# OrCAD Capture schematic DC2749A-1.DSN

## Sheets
1 PAGE2: size Custom; title: HIGH EFFICIENCY 4 PHASE 120A; rev: 1; company: TM
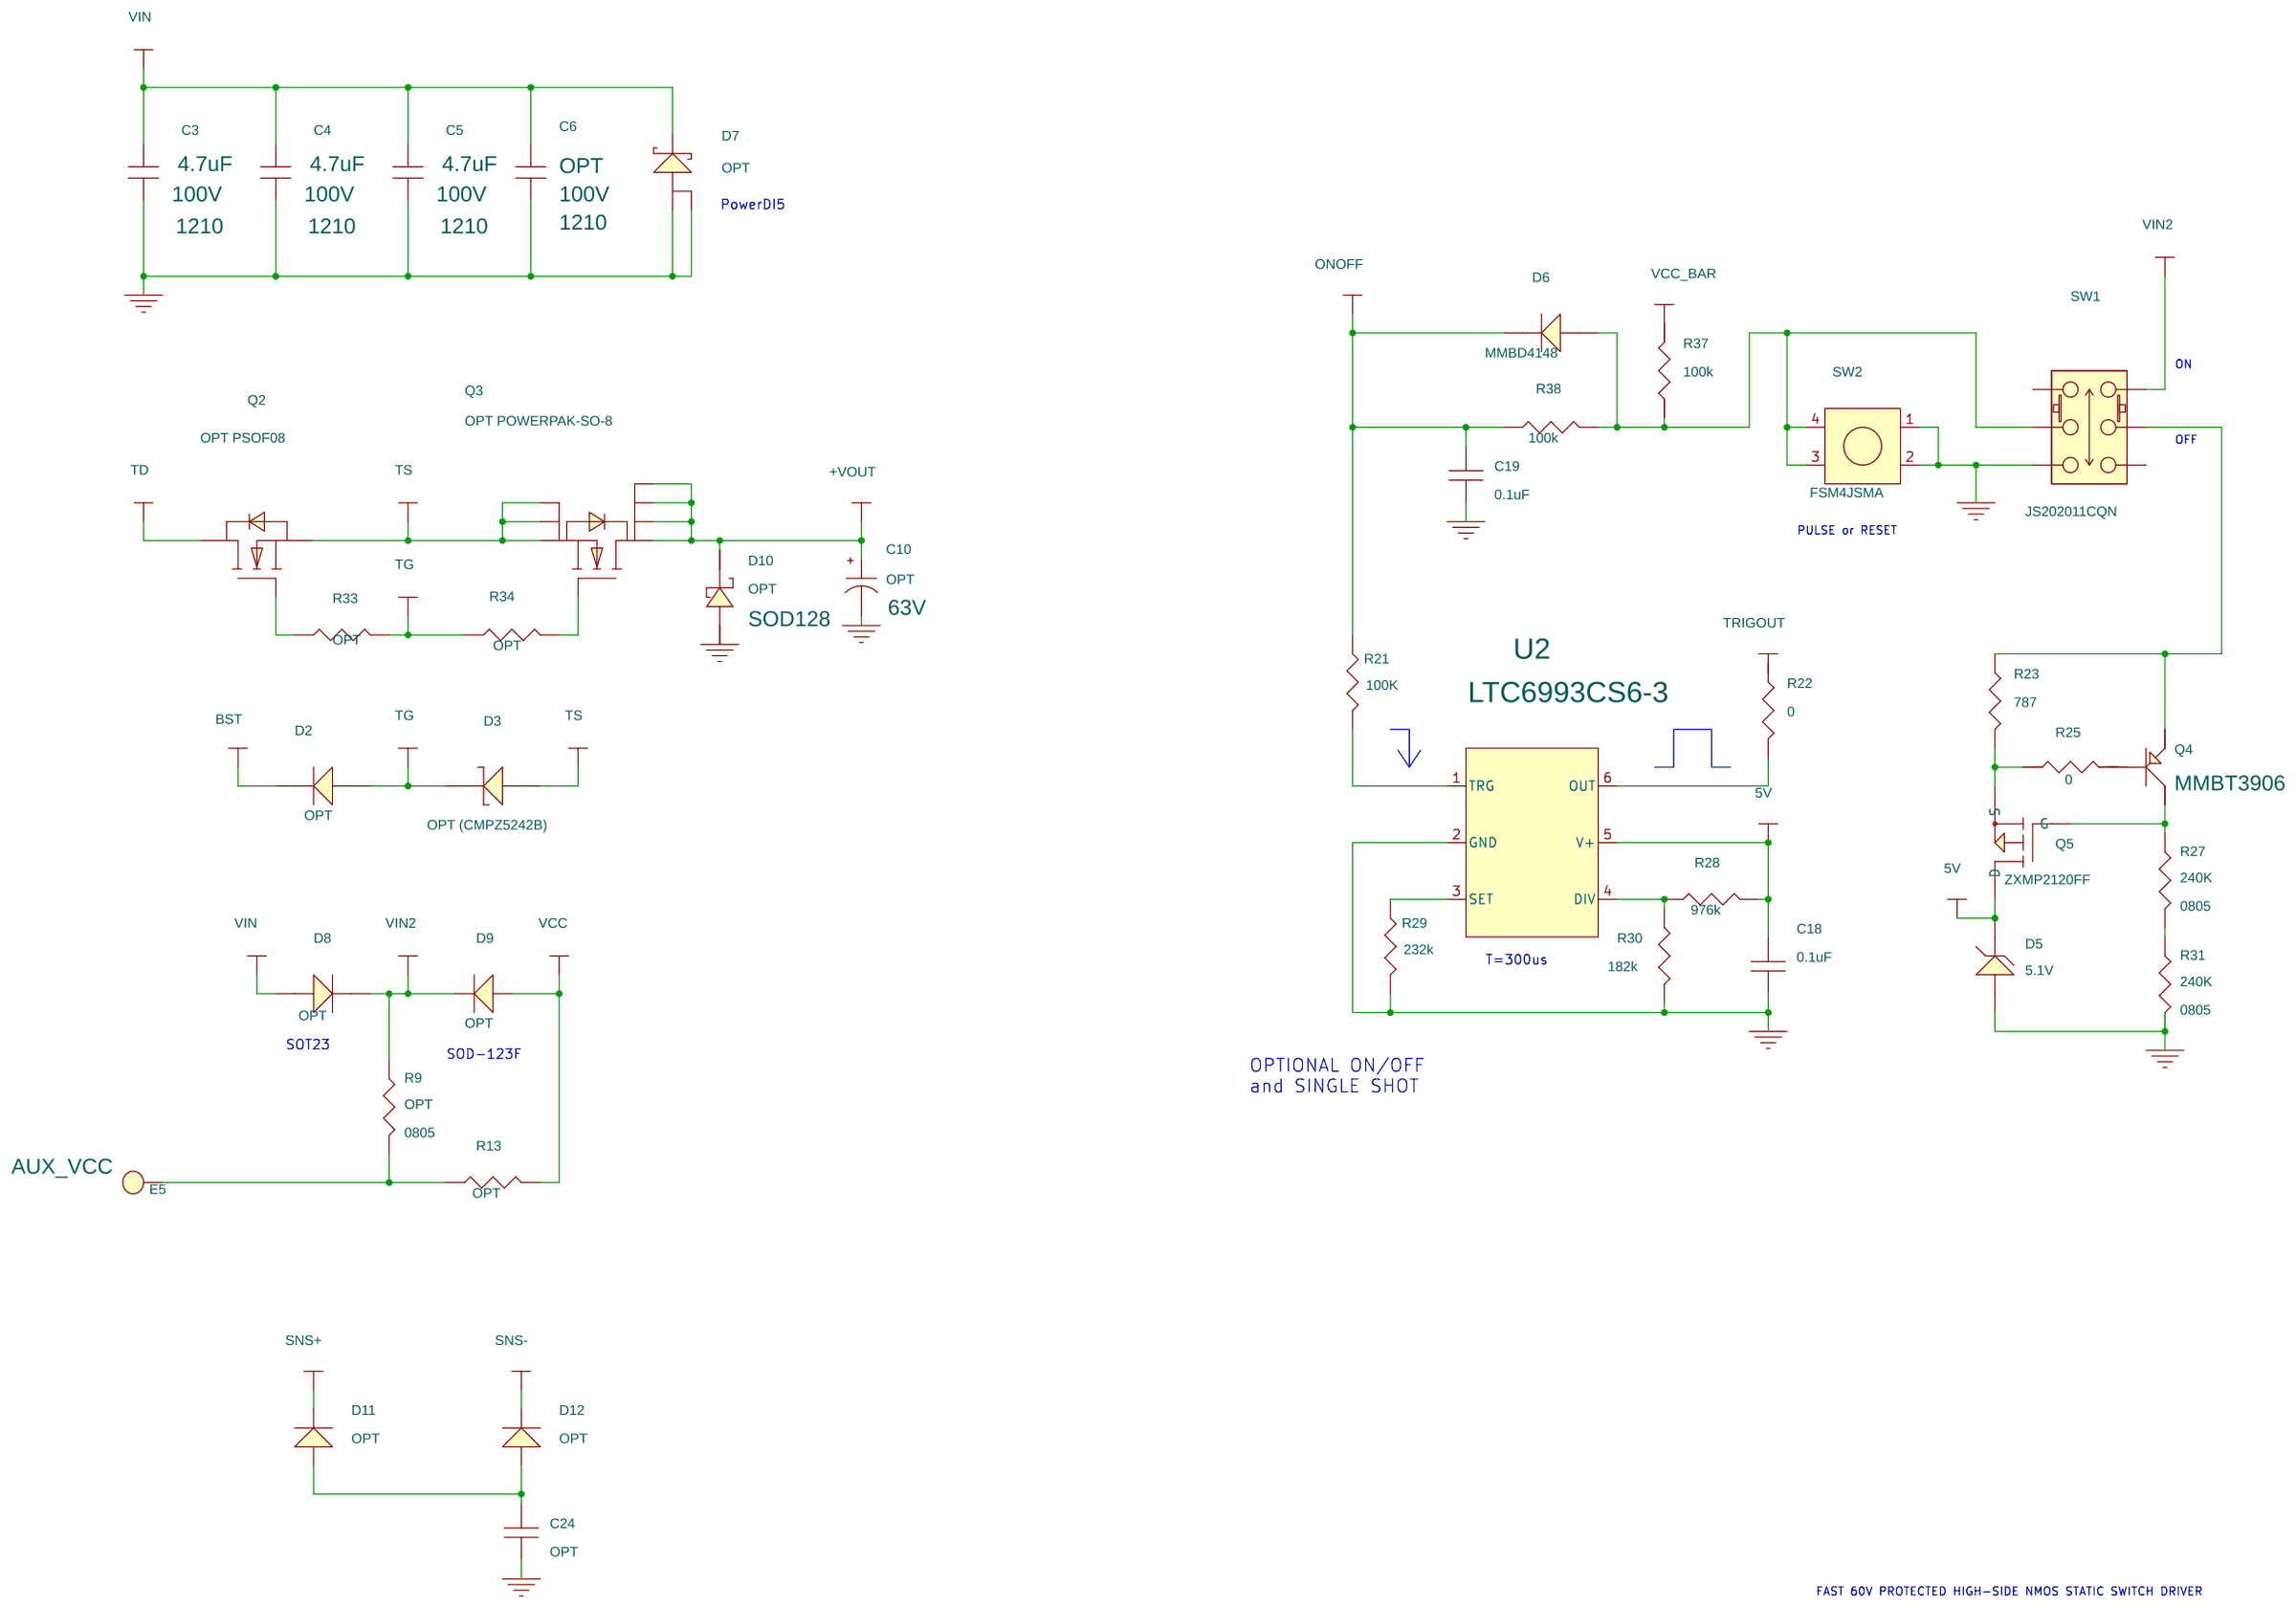
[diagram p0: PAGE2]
2 PAGE1: size Custom
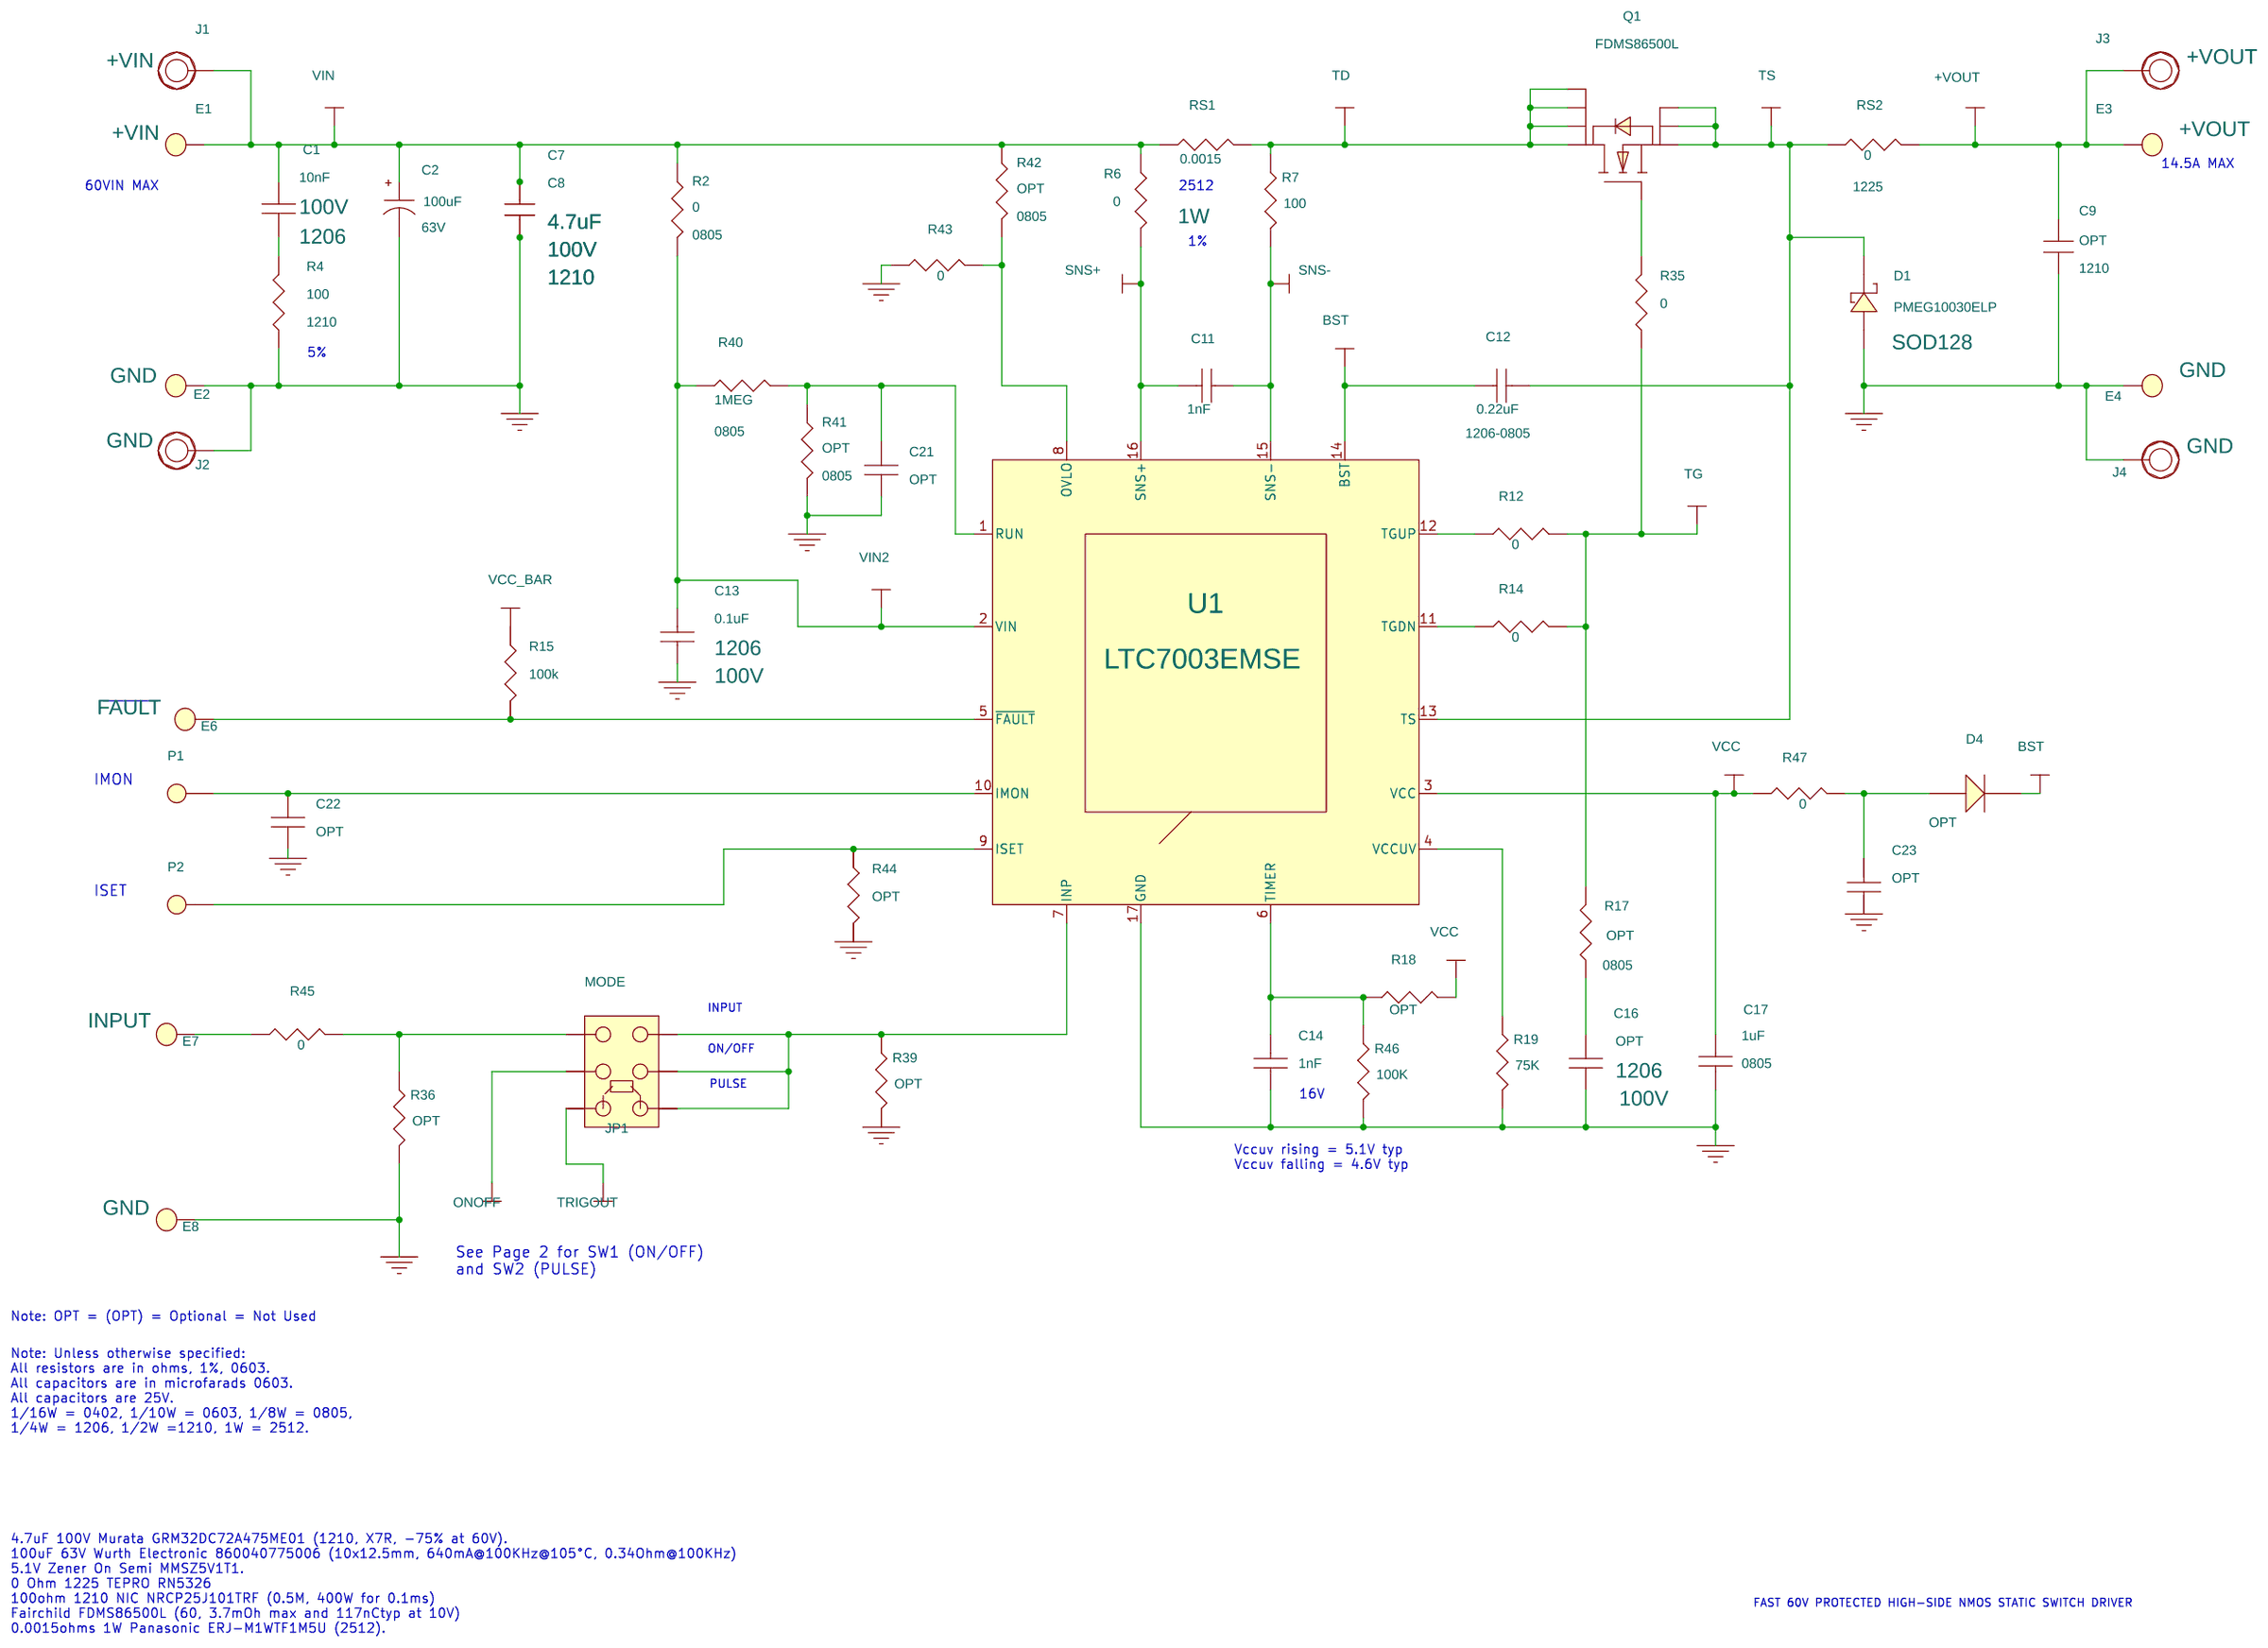
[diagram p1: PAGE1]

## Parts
sheet PAGE1
C1  10nF  [1206]
C2  100uF  [CAP-TH-EE-A-10D]
C7  4.7uF  [1210]
C8  4.7uF  [1210]
C9  OPT  [1210]
C11  1nF  [0603]
C12  0.22uF  [1206-0805]
C13  0.1uF  [1206]
C14  1nF  [0603]
C16  OPT  [1206]
C17  1uF  [0805]
C21  OPT  [0603]
C22  OPT  [0603]
C23  OPT  [0603]
D1  PMEG10030ELP  [SOD128]
D4  OPT  [SOT23]
E1  TURRET  [PAD150-094]
E2  TURRET  [PAD150-094]
E3  TURRET  [PAD150-094]
E4  TURRET  [PAD150-094]
E6  TURRET  [PAD150-094]
E7  TURRET  [PAD150-094]
E8  TURRET  [PAD150-094]
J1  Banana Jack  [KEYSTONE-575-4]
J2  Banana Jack  [KEYSTONE-575-4]
J3  Banana Jack  [KEYSTONE-575-4]
J4  Banana Jack  [KEYSTONE-575-4]
JP1  MODE  [HD2X3-079]
P1  TESTPAD  [PAD060-035]
P2  TESTPAD  [PAD060-035]
Q1  FDMS86500L  [POWERPAK-SO-8]
R2  0  [0805]
R4  100  [1210]
R6  0  [0603]
R7  100  [0603]
R12  0  [0603]
R14  0  [0603]
R15  100k  [0603]
R17  OPT  [0805]
R18  OPT  [0603]
R19  75K  [0603]
R35  0  [0603]
R36  OPT  [0603]
R39  OPT  [0603]
R40  1MEG  [0805]
R41  OPT  [0805]
R42  OPT  [0805]
R43  0  [0603]
R44  OPT  [0603]
R45  0  [0603]
R46  100K  [0603]
R47  0  [0603]
RS1  0.0015  [2512T]
RS2  0  [1225]
U1  LTC7003EMSE  [MSE16]
XJP1  2mm Ctrs.
sheet PAGE2
C3  4.7uF  [1210]
C4  4.7uF  [1210]
C5  4.7uF  [1210]
C6  OPT  [1210]
C10  OPT  [CAP-TH-10D]
C18  0.1uF  [0603]
C19  0.1uF  [0603]
C24  OPT  [0603]
D2  OPT  [SOT23]
D3  OPT (CMPZ5242B)  [SOT23]
D5  MMSZ5V1T1  [SOD-123]
D6  MMBD4148  [SOT23]
D7  OPT  [POWERDI5]
D8  OPT  [SOT23]
D9  OPT  [SOD-123F]
D10  OPT  [SOD128]
D11  OPT  [SOD323]
D12  OPT  [SOD323]
E5  TURRET  [PAD150-094]
Q2  OPT PSOF08  [PWR-PSOF08A-3P]
Q3  OPT POWERPAK-SO-8  [POWERPAK-SO-8]
Q4  MMBT3906  [SOT23B]
Q5  ZXMP2120FF  [SOT23A]
R9  OPT  [0805]
R13  OPT  [0603]
R21  100K  [0603]
R22  0  [0603]
R23  787  [0603]
R25  0  [0603]
R27  240K  [0805]
R28  976k  [0603]
R29  232k  [0603]
R30  182k  [0603]
R31  240K  [0805]
R33  OPT  [0603]
R34  OPT  [0603]
R37  100k  [0603]
R38  100k  [0603]
SW1  JS202011CQN  [JS202011]
SW2  FSM4JSMA  [SW-FSMJSMA]
U2  LTC6993CS6-3  [TSOT23-6]

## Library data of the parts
C1 C16 = 12061C104KAT2A_0: 1ST PART FIELD: 100V; 2ND PART FIELD: 10%, 0206; 3RD PART FIELD: X7R; 4TH PART FIELD: AVX; 7TH PART FIELD: CAP.
C2 = CAP-HVH-10X10.5: 1ST PART FIELD: 63V; 5TH PART FIELD: 10X20
C3-C8 = CAP1210: 1ST PART FIELD: 250V; 2ND PART FIELD: 20%, 1210; 3RD PART FIELD: X7R; 4TH PART FIELD: TDK; 7TH PART FIELD: CAP.; VOLTAGE: 100V
C9 = CAP1210: 1ST PART FIELD: 100V; 2ND PART FIELD: 20%, 1210; 3RD PART FIELD: X7R; 4TH PART FIELD: TDK; 7TH PART FIELD: CAP.
C11 C14 C18 C19 C21-C24 = 12061C104KAT2A_0: 1ST PART FIELD: 25V; 2ND PART FIELD: 10%, 0603; 3RD PART FIELD: NPO; 4TH PART FIELD: AVX; 5TH PART FIELD: 06033A471KAT2A; 7TH PART FIELD: CAP.
C12 = 12061C104KAT2A_0: 1ST PART FIELD: 25V; 2ND PART FIELD: 10%, 0805; 3RD PART FIELD: X7R; 4TH PART FIELD: AVX; 5TH PART FIELD: 0805; 7TH PART FIELD: CAP.
C13 = 12061C104KAT2A_0: 1ST PART FIELD: 200V; 2ND PART FIELD: 10%, 0206; 3RD PART FIELD: X7R; 4TH PART FIELD: AVX; 7TH PART FIELD: CAP.; VOLTAGE: 100V
C17 = TMK316BJ105KL: 1ST PART FIELD: 16V; 2ND PART FIELD: 10%, 0805; 3RD PART FIELD: X7R; 4TH PART FIELD: TAIYO TUDEN; 7TH PART FIELD: CAP.
D1 D10 = DIODE_SCHOTTKY_0
D4 D8 = CMPSH1-4_14
E1 = TURRET_2501-2: 7TH PART FIELD: HOLE,; 9TH PART FIELD: +VIN
E2 E4 = TURRET_2501-2: 7TH PART FIELD: HOLE,; 9TH PART FIELD: GND
E3 = TURRET_2501-2: 7TH PART FIELD: HOLE,; 9TH PART FIELD: +VOUT
E6 = TURRET_2501-2: 9TH PART FIELD: FAULT
E7 = TURRET_2501-2: 9TH PART FIELD: INPUT
E8 = TURRET_2501-2: 9TH PART FIELD: GND
J1 = E-KEY-575_0: 9th Part Field: +VIN
J2 J4 = E-KEY-575_0: 9th Part Field: GND
J3 = E-KEY-575_0: 9th Part Field: +VOUT
JP1 = hdr2X4_0: HEADER, 4PIN, DBL ROW 2mm; Part Number: SAMTEC TMM-104-02-L-D
P1 = P-TP_2
P2 = P-TP_3
Q1 Q3 = SI7456DP: 1ST PART FIELD: 150V; 2ND PART FIELD: POWERPAK SO-8; 3RD PART FIELD: N-CHANNEL; 5TH PART FIELD: Si7450DP; 7TH PART FIELD: FET; opt: *
R2 R9 R17 R27 R31 R40-R42 = AAC-0805: 2ND PART FIELD: 1%, 0805; 7TH PART FIELD: RES.
R4 = AAC-0805: 1ST PART FIELD: 0.5W; 2ND PART FIELD: 5%, 1210; 4TH PART FIELD: NIC; 5TH PART FIELD: NRCP25J101TRF; 7TH PART FIELD: RES.
R6 R7 R12-R15 R18 R19 R21-R23 R25 R28-R30 R33-R39 R43-R47 = AAC-0805: 1ST PART FIELD: 1/16W; 2ND PART FIELD: 1%, 0603; 5TH PART FIELD: CR16-xxxxFM; 7TH PART FIELD: RES.
RS1 = AAC-0805: 1ST PART FIELD: 1W; 2ND PART FIELD: 1%, 0805; 5TH PART FIELD: 1206; 7TH PART FIELD: RES.
RS2 = AAC-0805: 1ST PART FIELD: 1/2W; 2ND PART FIELD: 1%, 1210; 5TH PART FIELD: 1210; 7TH PART FIELD: RES.
U1 = LT1339_64: 3RD PART FIELD: ANALOG; 4TH PART FIELD: LINEAR TECH.; 5TH PART FIELD: LTC7000EMS16E; 7TH PART FIELD: I.C.
XJP1 = Samtec_2SN-BK-G: SHUNT; Part Number: SAMTEC 2SN-BK-G
C10 = CAP-HVH-10X10.5: 1ST PART FIELD: 63V; 5TH PART FIELD: 10X10.5
D2 = CMPSH1-4_12
D3 = CMPSH1-4_16
D5 = MMBZ5248BLT1_0: 1ST PART FIELD: 5.1V; 2ND PART FIELD: 5%, SOD123; 3RD PART FIELD: ZENER; 4TH PART FIELD: DIODES INC.; 7TH PART FIELD: DIODE
D6 = CMPSH1-4_11
D7 = DIODE-PDS3100
D9 D11 D12 = DIODE-CMMR1U-SOD123F
E5 = TURRET_2501-2: 9TH PART FIELD: AUX_VCC
Q2 = SI7456DP_3: 1ST PART FIELD: 150V; 2ND PART FIELD: POWERPAK SO-8; 3RD PART FIELD: N-CHANNEL; 5TH PART FIELD: Si7450DP; 7TH PART FIELD: FET; opt: *
Q4 = MMBT3906LT1_0: 2ND PART FIELD: SOT23; 3RD PART FIELD: PNP; 4TH PART FIELD: ZETEX; 5TH PART FIELD: FMMT718; 7TH PART FIELD: XSTR.
Q5 = MOSFET_P-DIODE_2
SW1 = SW_5: HEADER, 4PIN, DBL ROW 2mm
SW2 = BUTTON_0
U2 = LTC2400_2

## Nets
5V: C18.1 D5.1 Q5.D R28.2 R37.1 U2.5(V+)
GND: C2.2 C3.2 C4.2 C5.2 C6.2 C7.2 C8.2 C9.2 C10.2 C13.2 C14.2 C16.2 C17.2 C18.2 C19.2 C21.2 C22.2 C23.2 C24.2 D1.2(ANODE) D5.2 D7.2 D7.3 D10.2(ANODE) E2.1 E4.1 E8.1 J2.1 J4.1 R4.2 R19.2 R29.2 R30.2 R31.1 R36.2 R39.2 R41.1 R43.2 R44.2 R46.2 SW1.6 SW2.1 SW2.2 U1.17(GND) U2.2(GND)
VCC: C17.1 D9.2 R13.2 R15.1 R18.1 R47.1 U1.3(VCC)
VIN: C1.2 C2.1 C3.1 C4.1 C5.1 C6.1 C7.1 C8.1 D7.1 D8.1(A) E1.1 J1.1 R2.2 R6.1 R42.2 RS1.2
VIN2: C13.1 D8.3(K) D9.1 R2.1 R9.2 R40.2 SW1.1 U1.2(VIN)
+VOUT: C9.1 C10.1 D10.1(CATHODE) E3.1 J3.1 Q3.5 Q3.6 Q3.7 Q3.8 RS2.1
BST: C12.2 D2.3(K) D4.3(K) U1.14(BST)
ONOFF: C19.1 D6.3(K) JP1.4 R21.1 R38.2
SNS+: C11.1 D11.1 R6.2 U1.16(SNS+)
SNS-: C11.2 D12.1 R7.2 U1.15(SNS-)
TD: Q1.5 Q1.6 Q1.7 Q1.8 Q2.D R7.1 RS1.1
TG: D2.1(A) D3.3(K) R12.2 R14.2 R17.1 R33.2 R34.1 R35.1
TRIGOUT: JP1.6 R22.1
TS: C12.1 D1.1(CATHODE) D3.1(A) Q1.1 Q1.2 Q1.3 Q2.S Q3.1 Q3.2 Q3.3 RS2.2 U1.13(TS)
N19054060: E6.1 R15.2 U1.5(~{FAULT})
N19054068: C14.1 R18.2 R46.1 U1.6(TIMER)
N19054099: C22.1 P1.1(A) U1.10(IMON)
N19054138: C21.1 R40.1 R41.2 U1.1(RUN)
N19054192: C16.1 R17.2
N19054262: R42.1 R43.1 U1.8(OVLO)
N19054491: Q1.4 R35.2
N19054777: P2.1(A) R44.1 U1.9(ISET)
N19054856: C1.1 R4.1
N19054862: R12.1 U1.12(TGUP)
N19054937: R14.1 U1.11(TGDN)
N19056424: E5.1 R9.1 R13.1
N19056950: Q3.4 R34.2
N19056982: Q2.G R33.1
N19060184: JP1.2 R36.1 R45.2
N19060223: JP1.1 JP1.3 JP1.5 R39.1 U1.7(INP)
N19061333: E7.1 R45.1
N19061526: R19.1 U1.4(VCCUV)
N19068396: R28.1 R30.1 U2.4(DIV)
N19068478: D6.1(A) R37.2 R38.1 SW1.5 SW2.3 SW2.4
N19068494: Q4.E R23.1 SW1.2
N19068588: R21.2 U2.1(TRG)
N19068610: R27.1 R31.2
N19068630: R22.2 U2.6(OUT)
N19068638: Q5.S R23.2 R25.2
N19068729: Q4.C Q5.G R27.2
N19068794: R29.1 U2.3(SET)
N19068796: Q4.B R25.1
N19081929: C23.1 D4.1(A) R47.2
N19103824: C24.1 D11.2 D12.2

Not connected (* = marked no-connect by the designer): SW1 3 4

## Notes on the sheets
sheet 1
- PowerDI5
- ON
- OFF
- PULSE or RESET
- T=300us
- SOT23
- SOD-123F
- OPTIONAL ON/OFF
  and SINGLE SHOT
- FAST 60V PROTECTED HIGH-SIDE NMOS STATIC SWITCH DRIVER
sheet 2
- 14.5A MAX
- 60VIN MAX
- 2512
- 1%
- 5%
- IMON
- ISET
- INPUT
- ON/OFF
- PULSE
- 16V
- Vccuv rising = 5.1V typ
  Vccuv falling = 4.6V typ
- See Page 2 for SW1 (ON/OFF)
  and SW2 (PULSE)
- Note: OPT = (OPT) = Optional = Not Used
- Note: Unless otherwise specified:
  All resistors are in ohms, 1%, 0603.
  All capacitors are in microfarads 0603.
  All capacitors are 25V.
  1/16W = 0402, 1/10W = 0603, 1/8W = 0805,
  1/4W = 1206, 1/2W =1210, 1W = 2512.
- 4.7uF 100V Murata GRM32DC72A475ME01 (1210, X7R, -75% at 60V).
  100uF 63V Wurth Electronic 860040775006 (10x12.5mm, 640mA@100KHz@105°C, 0.34Ohm@100KHz)
  5.1V Zener On Semi MMSZ5V1T1.
  0 Ohm 1225 TEPRO RN5326
  100ohm 1210 NIC NRCP25J101TRF (0.5M, 400W for 0.1ms)
  Fairchild FDMS86500L (60, 3.7mOh max and 117nCtyp at 10V)
  0.0015ohms 1W Panasonic ERJ-M1WTF1M5U (2512).
- FAST 60V PROTECTED HIGH-SIDE NMOS STATIC SWITCH DRIVER
